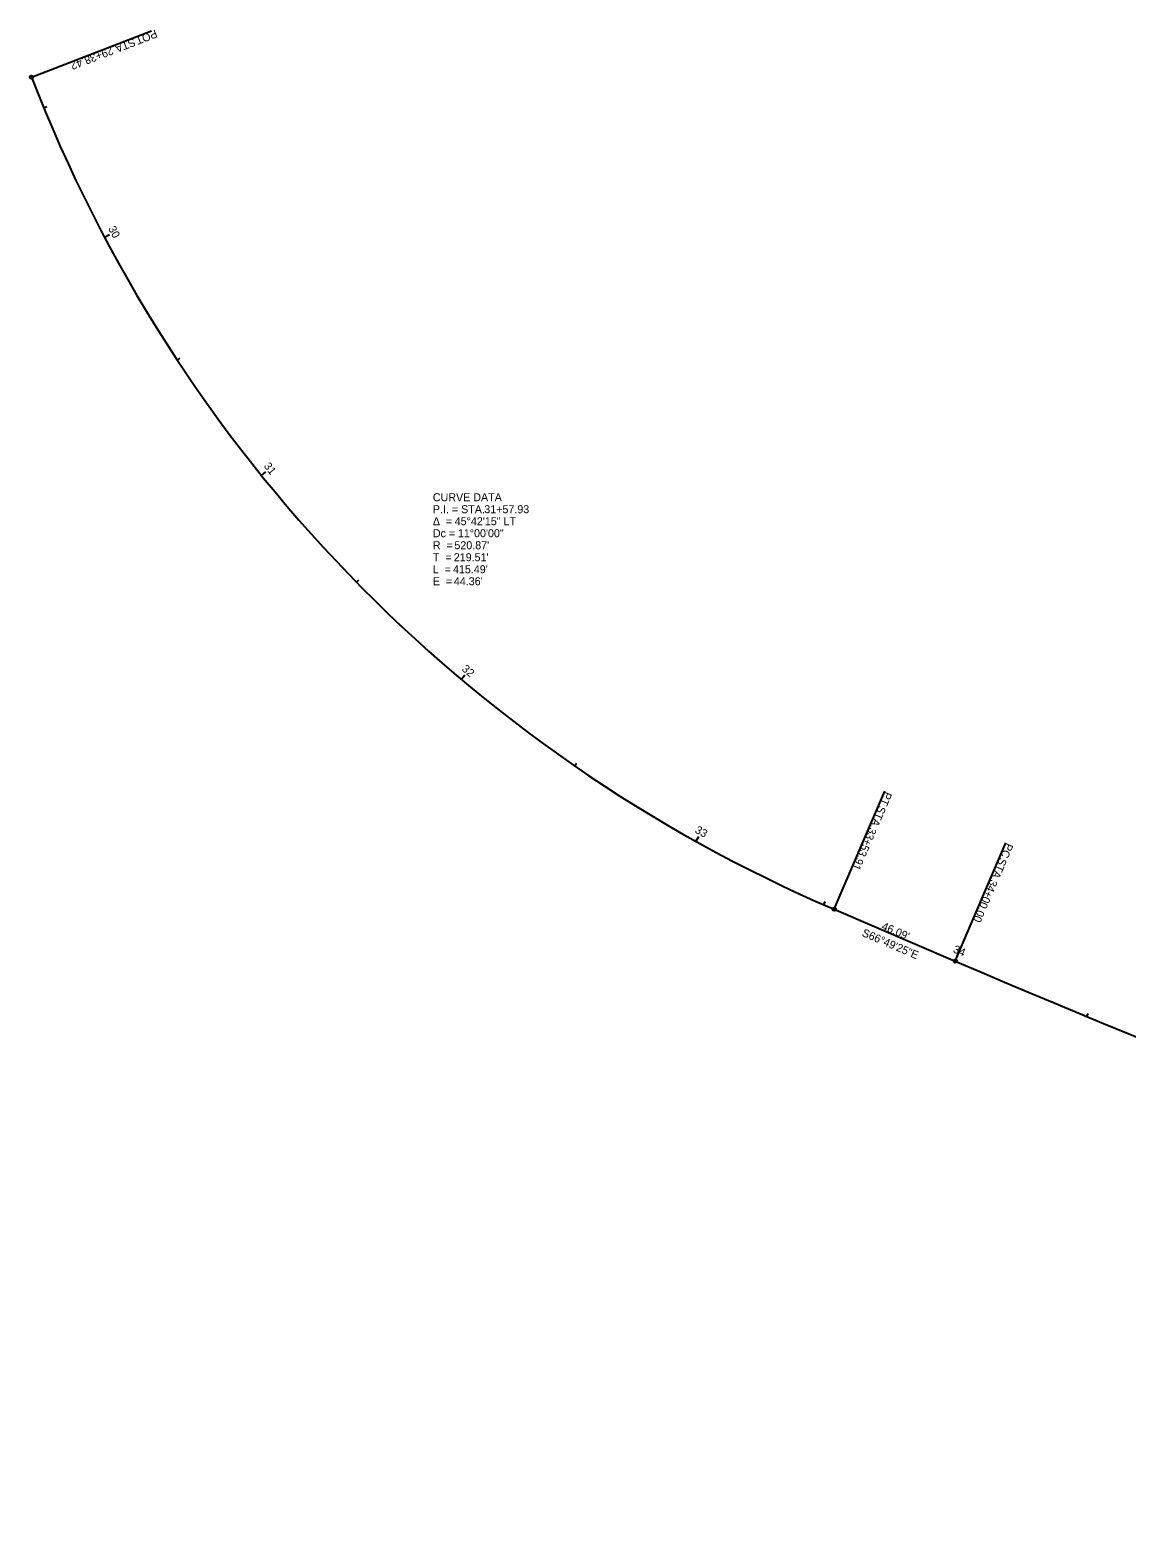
# Model space of a CAD drawing. Extents: x 1821160 to 1822741, y 497996 to 498758.
# Drawn here: x 1821160 to 1821543, y 498150 to 498672 of the extents above; entities that cross this region are included whole.
import ezdxf

# ---------------------------------------------------------------- set-up
doc = ezdxf.new("R2010")
doc.units = 0
for name, color, linetype in [('LT_X_Luminaires', 7, 'Continuous'), ('SC_Scratch1', 7, 'Continuous'), ('SC_Scratch20', 7, 'Continuous'), ('SV_P_Mon_Cells_Set', 7, 'Continuous'), ('SV_X_Control_Cells_Found', 7, 'Continuous'), ('SV_X_Mon_Cells_Found', 7, 'Continuous')]:
    doc.layers.add(name, color=color, linetype=linetype)

msp = doc.modelspace()

# ---------------------------------------------------------------- linework, layer by layer
at = {"layer": 'SC_Scratch1'}
for p, q in [((1821164.43, 498644.57), (1821165.54, 498645.02)), ((1821185.67, 498599.32), (1821187.44, 498600.26)), ((1821211.14, 498556.32), (1821212.15, 498556.98)), ((1821240.62, 498515.96), (1821242.18, 498517.21)), ((1821273.83, 498478.61), (1821274.69, 498479.45)), ((1821310.47, 498444.61), (1821311.76, 498446.14)), ((1821350.2, 498414.28), (1821350.88, 498415.27)), ((1821392.65, 498387.91), (1821393.63, 498389.65)), ((1821437.44, 498365.72), (1821437.92, 498366.82)), ((1821483.4, 498346.02), (1821484.19, 498347.86)), ((1821529.48, 498326.62), (1821529.94, 498327.73))]:
    msp.add_line(p, q, dxfattribs=at)
at = {"layer": 'SV_P_Mon_Cells_Set'}
msp.add_line((1821441.03, 498364.16), (1821483.4, 498346.02), dxfattribs=at)
for centre, radius, start, end in [((1821646.02, 498843), 520.87, 201.1194, 246.8236), ((1823136.37, 502207.06), 4199.99, 246.82358, 255.00869)]:
    msp.add_arc(centre, radius, start, end, dxfattribs=at)
at = {"layer": 'SV_X_Control_Cells_Found'}
for p, q in [((1821160.14, 498655.32), (1821202.12, 498671.54)), ((1821441.03, 498364.16), (1821458.74, 498405.53)), ((1821483.4, 498346.02), (1821501.11, 498387.39))]:
    msp.add_line(p, q, dxfattribs=at)
for centre in [(1821160.14, 498655.32), (1821441.03, 498364.16), (1821483.4, 498346.02)]:
    msp.add_circle(centre, 0.6, dxfattribs=at)

# ---------------------------------------------------------------- texts
at = {"layer": 'LT_X_Luminaires'}
for s, p in [('CURVE DATA', (1821300.58, 498506.94)), ('P.I. = STA. ', (1821300.58, 498502.74)), ('31+57.93', (1821318.58, 498502.74)), ('Δ  = ', (1821300.58, 498498.54)), ('45°42\'15" LT', (1821308.23, 498498.54)), ('Dc = ', (1821300.58, 498494.34)), ('11°00\'00"', (1821309.33, 498494.34)), ('R  = ', (1821300.58, 498490.14)), ("520.87'", (1821308.12, 498490.14)), ('T  = ', (1821300.58, 498485.94)), ('L  = ', (1821300.58, 498481.74)), ("415.49'", (1821307.62, 498481.74)), ("219.51'", (1821307.9, 498485.94)), ('E  = ', (1821300.58, 498477.54)), ("44.36'", (1821307.93, 498477.54))]:
    msp.add_text(s, height=2.8, dxfattribs=at).set_placement(p)
at = {"layer": 'SC_Scratch1'}
for s, rotation, p in [('30', 297.8932, (1821186.87, 498602.39)), ('31', 308.8933, (1821241.25, 498519.17)), ('32', 319.8933, (1821310.48, 498447.87)), ('33', 330.8933, (1821392.05, 498391.1)), ('34', 336.8236, (1821482.39, 498349.17))]:
    msp.add_text(s, height=2.8, rotation=rotation, dxfattribs=at).set_placement(p)
at = {"layer": 'SC_Scratch20'}
msp.add_text("46.09'", height=2.8, rotation=336.8236, dxfattribs=at).set_placement((1821457.34, 498357.22))
at = {"layer": 'SV_X_Control_Cells_Found'}
for s, rotation, p in [(' STA. ', 201.1194, (1821196.81, 498669.45)), ('POT', 201.1194, (1821203.46, 498672.02)), ('29+38.42', 201.1194, (1821188.12, 498666.09)), ('PT', 246.8236, (1821458.79, 498405.56)), (' STA. ', 246.8236, (1821457.08, 498401.56)), ('33+53.91', 246.8236, (1821453.41, 498392.99)), ('PC', 246.8236, (1821501.23, 498387.58)), (' STA. ', 246.8236, (1821499.42, 498383.35)), ('34+00.00', 246.8236, (1821495.75, 498374.78))]:
    msp.add_text(s, height=2.8, rotation=rotation, dxfattribs=at).set_placement(p)
at = {"layer": 'SV_X_Mon_Cells_Found'}
msp.add_text('S66°49\'25"E', height=2.8, rotation=336.8236, dxfattribs=at).set_placement((1821450.48, 498354.89))

doc.saveas('drawing.dxf')
